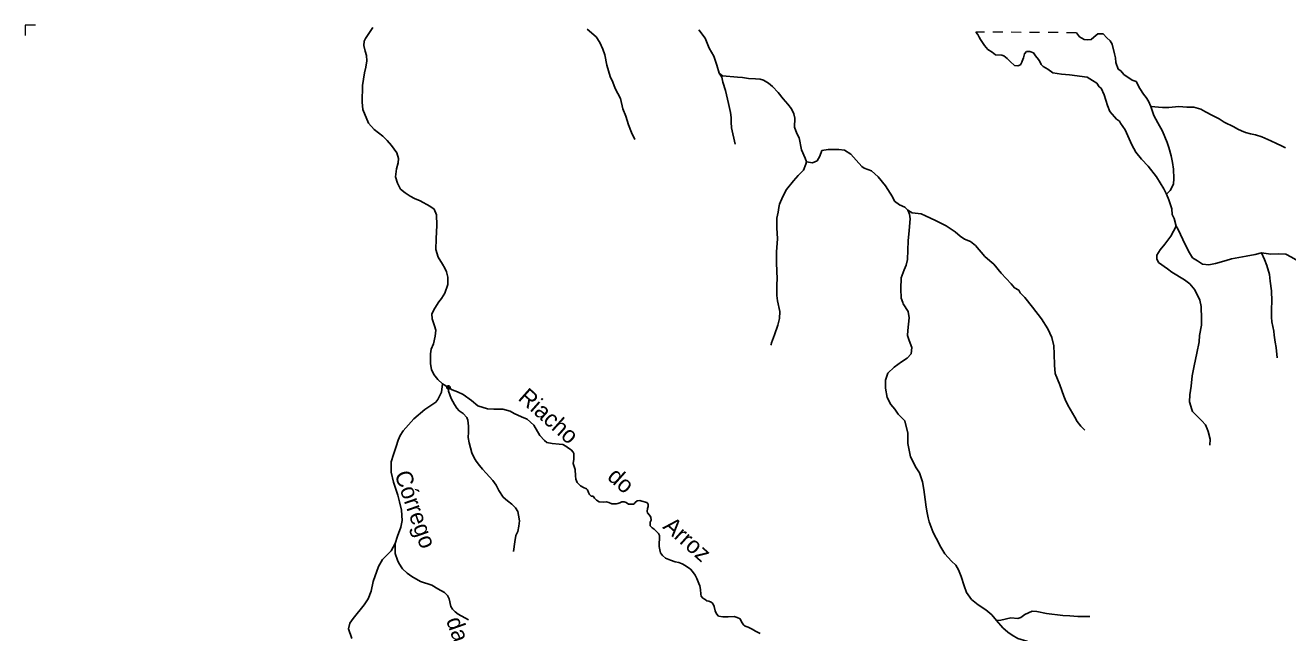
# Model space of a CAD drawing. Extents: x 717.8 to 772.7, y 8672.2 to 8728.
# Drawn here: x 718.16 to 733.27, y 8720.68 to 8727.96 of the extents above; entities that cross this region are included whole.
import ezdxf
from ezdxf.enums import TextEntityAlignment as Align

# ---------------------------------------------------------------- set-up
doc = ezdxf.new("R2010")
doc.units = 0
doc.header["$LTSCALE"] = 0.08
doc.header["$PDMODE"] = 32
doc.header["$PDSIZE"] = 0.04
doc.linetypes.add('LONG_DASHED', pattern=[7.5, 6, -1.5])
doc.linetypes.add('SHORT_DASHED', pattern=[2.7, 1.5, -1.2])
for name, color, linetype, lineweight in [('3', 7, 'LONG_DASHED', 25), ('62', 7, 'SHORT_DASHED', 13), ('63', 7, 'Continuous', 13), ('9', 7, 'LONG_DASHED', 25)]:
    doc.layers.add(name, color=color, linetype=linetype, lineweight=lineweight)
doc.layers.add('61', color=7, linetype='Continuous')

msp = doc.modelspace()

# ---------------------------------------------------------------- linework, layer by layer
at = {"layer": '3'}
for points in [[(729.5397, 8727.8794), (729.5617, 8727.8497), (729.5791, 8727.8187), (729.597, 8727.7887), (729.6416, 8727.7164), (729.6813, 8727.6679), (729.7347, 8727.6398), (729.7754, 8727.6068), (729.8491, 8727.6029), (729.8763, 8727.5932), (729.9162, 8727.5606), (729.9509, 8727.5262), (730.0014, 8727.4787), (730.0408, 8727.4753), (730.0745, 8727.487), (730.0918, 8727.5192), (730.0953, 8727.5317), (730.1113, 8727.5704), (730.1237, 8727.6172), (730.146, 8727.6441), (730.1864, 8727.6477), (730.2292, 8727.63), (730.2531, 8727.5941), (730.2889, 8727.5513), (730.3044, 8727.5246), (730.3228, 8727.4884), (730.3441, 8727.4647), (730.4023, 8727.4329), (730.4604, 8727.3889), (730.5631, 8727.3733), (730.6619, 8727.3676), (730.8702, 8727.3388), (730.9371, 8727.2981), (730.9874, 8727.2669), (731.0151, 8727.2208), (731.0384, 8727.2073), (731.0774, 8727.1266), (731.1164, 8726.999), (731.144, 8726.9253), (731.1978, 8726.8626), (731.2233, 8726.8357), (731.2588, 8726.8116), (731.2694, 8726.7875), (731.3261, 8726.706), (731.4068, 8726.5266), (731.4535, 8726.4401), (731.5226, 8726.3582), (731.6004, 8726.2712), (731.7036, 8726.143), (731.7892, 8726), (731.8214, 8725.9366)], [(731.6344, 8726.9883), (731.6056, 8727.0505), (731.5785, 8727.0961), (731.545, 8727.1365), (731.5028, 8727.2046), (731.4597, 8727.2855), (731.4098, 8727.3038), (731.3111, 8727.3709), (731.2733, 8727.4132), (731.2443, 8727.4359), (731.2163, 8727.5142), (731.2101, 8727.5703), (731.1985, 8727.6188), (731.1728, 8727.7335), (731.1492, 8727.7735), (731.1074, 8727.8101), (731.0617, 8727.8565), (731.0009, 8727.8559), (730.9504, 8727.8162), (730.9204, 8727.79), (730.8816, 8727.7849), (730.8347, 8727.79), (730.7796, 8727.8223), (730.7433, 8727.8704)], [(731.8214, 8725.9366), (731.864, 8725.9813), (731.9058, 8726.0583), (731.9089, 8726.1241), (731.9051, 8726.2374), (731.8938, 8726.3169), (731.8773, 8726.3978), (731.848, 8726.4953), (731.8282, 8726.5539), (731.7745, 8726.6933), (731.7198, 8726.7934), (731.6718, 8726.8797), (731.6344, 8726.9883)]]:
    msp.add_lwpolyline(points, dxfattribs=at)
at = {"layer": '62'}
msp.add_line((730.7433, 8727.8704), (729.5397, 8727.8794), dxfattribs=at)
at = {"layer": '63'}
msp.add_lwpolyline([(718.2841, 8727.9605), (718.1609, 8727.9605), (718.1609, 8727.8391)], dxfattribs=at)
at = {"layer": '9'}
msp.add_line((723.1552, 8723.6644), (723.227, 8723.6225), dxfattribs=at)
for points in [[(722.322, 8727.9322), (722.2324, 8727.8021), (722.2195, 8727.7681), (722.2135, 8727.7167), (722.2294, 8727.6501), (722.246, 8727.5995), (722.2483, 8727.5344), (722.2369, 8727.4588), (722.2231, 8727.3923), (722.1974, 8727.2388), (722.195, 8727.04), (722.2021, 8726.9507), (722.2698, 8726.7889), (722.3393, 8726.7126), (722.4415, 8726.6316), (722.4928, 8726.578), (722.5461, 8726.5218), (722.6097, 8726.4323), (722.6294, 8726.3627), (722.6233, 8726.3113), (722.6044, 8726.2402), (722.5932, 8726.1457), (722.6166, 8726.0686), (722.6514, 8725.9975), (722.7074, 8725.9517), (722.7671, 8725.912), (722.8192, 8725.884), (722.8896, 8725.8568), (723.0027, 8725.795), (723.0541, 8725.7564), (723.0828, 8725.6914), (723.0864, 8725.5662), (723.0789, 8725.4021), (723.0774, 8725.2735), (723.1053, 8725.1805), (723.1536, 8725.0986), (723.1819, 8725.0491), (723.2034, 8725.0053), (723.22, 8724.9426), (723.2177, 8724.8548), (723.185, 8724.7529), (723.1427, 8724.6864), (723.1112, 8724.6466), (723.0656, 8724.5714), (723.0297, 8724.5031), (723.0306, 8724.4419), (723.058, 8724.3606), (723.0759, 8724.3076), (723.0688, 8724.2369), (723.0477, 8724.1452), (723.0208, 8724.0814), (723.0118, 8724.0236), (723.0119, 8723.9035), (723.0231, 8723.8363), (723.0511, 8723.7781), (723.0984, 8723.7185), (723.1552, 8723.6644)], [(725.4572, 8726.591), (725.417, 8726.6763), (725.3822, 8726.7678), (725.3479, 8726.8732), (725.3139, 8726.9585), (725.285, 8727.0834), (725.2205, 8727.2033), (725.194, 8727.2796), (725.1626, 8727.3463), (725.124, 8727.4836), (725.0971, 8727.6047), (725.0753, 8727.6749), (725.0367, 8727.7542), (724.9966, 8727.8208), (724.8886, 8727.913)], [(726.4674, 8727.3874), (726.4401, 8727.4832), (726.4051, 8727.5884), (726.3491, 8727.6864), (726.3001, 8727.8055), (726.2233, 8727.9038)], [(726.6587, 8726.5378), (726.6148, 8726.7321), (726.6096, 8726.7982), (726.609, 8726.8538), (726.602, 8726.9159), (726.5803, 8727.0224), (726.5423, 8727.1791), (726.5119, 8727.2774), (726.4973, 8727.3383), (726.4674, 8727.3874)], [(727.5112, 8726.3234), (727.4969, 8726.3665), (727.4535, 8726.4666), (727.4249, 8726.6118), (727.3978, 8726.6646), (727.3708, 8726.738), (727.3722, 8726.8457), (727.3605, 8726.9), (727.3349, 8726.9608), (727.2872, 8727.0165), (727.2315, 8727.0789), (727.1714, 8727.1566), (727.1055, 8727.2268), (727.0586, 8727.2671), (726.9985, 8727.3031), (726.958, 8727.3133), (726.9008, 8727.3202), (726.8174, 8727.3219), (726.7468, 8727.334), (726.6879, 8727.3381), (726.5084, 8727.3564), (726.4674, 8727.3874)], [(733.2448, 8726.4901), (733.1997, 8726.5172), (733.1366, 8726.5443), (733.0699, 8726.5773), (732.9611, 8726.6224), (732.886, 8726.6482), (732.8277, 8726.6608), (732.7657, 8726.6765), (732.7178, 8726.6974), (732.6758, 8726.7159), (732.6275, 8726.7429), (732.5129, 8726.7986), (732.4527, 8726.8386), (732.3722, 8726.8779), (732.288, 8726.9229), (732.2346, 8726.9568), (732.1498, 8726.9778), (732.0636, 8726.9809), (731.968, 8726.9874), (731.8479, 8726.9767), (731.7741, 8726.9752), (731.6344, 8726.9883)], [(728.7248, 8725.7465), (728.6892, 8725.7801), (728.6241, 8725.8074), (728.5648, 8725.8522), (728.5413, 8725.9064), (728.457, 8726.0361), (728.3719, 8726.1454), (728.2909, 8726.2158), (728.2026, 8726.2466), (728.174, 8726.2678), (728.1059, 8726.3456), (728.0436, 8726.4159), (727.9671, 8726.464), (727.9006, 8726.4717), (727.773, 8726.4725), (727.6973, 8726.4585), (727.6705, 8726.3918), (727.639, 8726.3368), (727.584, 8726.3133), (727.5112, 8726.3234)], [(727.5112, 8726.3234), (727.5053, 8726.2946), (727.4769, 8726.2249), (727.4136, 8726.161), (727.3567, 8726.0965), (727.2743, 8725.9916), (727.2281, 8725.9081), (727.1892, 8725.8189), (727.1797, 8725.7774), (727.1734, 8725.7196), (727.1588, 8725.6513), (727.1554, 8725.5324), (727.1643, 8725.4004), (727.1549, 8725.2449), (727.1549, 8725.1125), (727.1603, 8724.9225), (727.1574, 8724.8549), (727.1574, 8724.7214), (727.1673, 8724.6589), (727.195, 8724.5307), (727.1892, 8724.4463), (727.1684, 8724.3683), (727.1292, 8724.2505), (727.0922, 8724.1551), (727.0882, 8724.1346), (727.0859, 8724.1289)], [(731.9365, 8725.5542), (731.912, 8725.645), (731.8906, 8725.6939), (731.8848, 8725.761), (731.8484, 8725.8709), (731.8214, 8725.9366)], [(729.7852, 8720.83), (729.7311, 8720.8969), (729.6597, 8720.9583), (729.5679, 8721.0175), (729.4869, 8721.0822), (729.4283, 8721.1678), (729.401, 8721.2461), (729.3626, 8721.3571), (729.3336, 8721.4372), (729.2982, 8721.4917), (729.2496, 8721.5429), (729.169, 8721.6275), (729.1204, 8721.707), (729.0641, 8721.818), (729.0297, 8721.8831), (728.979, 8722.0123), (728.9704, 8722.0616), (728.9557, 8722.1219), (728.9453, 8722.1899), (728.9345, 8722.2815), (728.9182, 8722.4001), (728.9025, 8722.4932), (728.8661, 8722.5996), (728.8264, 8722.6589), (728.7555, 8722.7911), (728.7237, 8722.95), (728.7236, 8723.074), (728.6912, 8723.223), (728.6084, 8723.303), (728.5679, 8723.3617), (728.5238, 8723.4171), (728.4797, 8723.5016), (728.4575, 8723.6121), (728.4589, 8723.7083), (728.4859, 8723.7946), (728.5615, 8723.8648), (728.6479, 8723.9295), (728.7175, 8723.9712), (728.7636, 8724.0255), (728.7727, 8724.1003), (728.7433, 8724.1824), (728.722, 8724.2422), (728.7241, 8724.304), (728.7433, 8724.457), (728.7288, 8724.5325), (728.6693, 8724.6243), (728.6639, 8724.6404), (728.645, 8724.6909), (728.6423, 8724.8024), (728.6461, 8724.9351), (728.6806, 8725.0324), (728.7049, 8725.0881), (728.7211, 8725.156), (728.7292, 8725.379), (728.7414, 8725.5007), (728.7525, 8725.6426), (728.7434, 8725.6973), (728.7248, 8725.7465)], [(730.8437, 8723.1092), (730.7945, 8723.1582), (730.7514, 8723.2142), (730.7263, 8723.2673), (730.6416, 8723.4107), (730.6087, 8723.4766), (730.5919, 8723.5187), (730.5452, 8723.6551), (730.4895, 8723.7909), (730.4809, 8723.8886), (730.4755, 8724.0235), (730.4721, 8724.1195), (730.449, 8724.219), (730.4021, 8724.3239), (730.326, 8724.4423), (730.2177, 8724.5827), (730.1257, 8724.7013), (730.071, 8724.756), (730.0549, 8724.7863), (730.0016, 8724.8161), (729.9635, 8724.8631), (729.8445, 8724.9926), (729.754, 8725.0981), (729.7055, 8725.1377), (729.6472, 8725.1905), (729.5346, 8725.3211), (729.4756, 8725.3706), (729.4047, 8725.3987), (729.352, 8725.4358), (729.2931, 8725.4874), (729.1862, 8725.5573), (729.0554, 8725.6236), (728.936, 8725.6795), (728.8833, 8725.7014), (728.7791, 8725.7144), (728.7248, 8725.7465)], [(732.3416, 8722.9313), (732.3434, 8723.0012), (732.3195, 8723.0931), (732.3086, 8723.1259), (732.2884, 8723.1739), (732.2455, 8723.2234), (732.1343, 8723.3353), (732.1266, 8723.3583), (732.0984, 8723.4513), (732.0992, 8723.532), (732.116, 8723.6371), (732.1278, 8723.7606), (732.1513, 8723.8792), (732.1858, 8724.0322), (732.2144, 8724.1685), (732.2161, 8724.2424), (732.2413, 8724.3686), (732.2397, 8724.4443), (732.2355, 8724.5897), (732.2195, 8724.6654), (732.1606, 8724.7899), (732.101, 8724.8621), (732.0365, 8724.9104), (731.8842, 8725.0034), (731.8328, 8725.0408), (731.7278, 8725.1192), (731.7051, 8725.1632), (731.7051, 8725.2077), (731.7471, 8725.2683), (731.8002, 8725.3379), (731.8716, 8725.4329), (731.9365, 8725.5542)], [(731.9365, 8725.5542), (731.9626, 8725.5148), (732.016, 8725.394), (732.0859, 8725.2557), (732.1331, 8725.1761), (732.1911, 8725.1376), (732.2523, 8725.0999), (732.3267, 8725.0909), (732.4101, 8725.1062), (732.5356, 8725.1412), (732.599, 8725.1618), (732.7767, 8725.195), (732.8843, 8725.2147), (732.9591, 8725.2348)], [(733.1446, 8723.9779), (733.1334, 8724.0985), (733.1218, 8724.1641), (733.1123, 8724.2483), (733.1067, 8724.2949), (733.0834, 8724.4061), (733.0785, 8724.4653), (733.0785, 8724.559), (733.0825, 8724.6551), (733.0798, 8724.7797), (733.0628, 8724.8945), (733.0546, 8724.9758), (733.0241, 8725.0812), (732.9948, 8725.1562), (732.9591, 8725.2348)], [(733.9818, 8724.0121), (733.9155, 8724.1229), (733.8999, 8724.2479), (733.904, 8724.3603), (733.9087, 8724.4377), (733.9038, 8724.5924), (733.8842, 8724.6408), (733.8599, 8724.665), (733.7704, 8724.7214), (733.7217, 8724.7601), (733.6926, 8724.7988), (733.6293, 8724.881), (733.563, 8724.9779), (733.4599, 8725.0998), (733.318, 8725.181), (733.251, 8725.2182), (733.1676, 8725.221), (733.0707, 8725.2174), (732.9591, 8725.2348)], [(722.6255, 8722.9902), (722.6468, 8723.0456), (722.6837, 8723.1031), (722.8128, 8723.2464), (722.9426, 8723.3564), (723.0753, 8723.4437), (723.1009, 8723.4778), (723.12, 8723.5189), (723.1441, 8723.5644), (723.1552, 8723.6644)], [(724.0061, 8721.6565), (724.0199, 8721.7711), (724.0338, 8721.8483), (724.0571, 8721.8974), (724.071, 8721.9605), (724.0779, 8722.0236), (724.0661, 8722.0915), (724.0591, 8722.136), (724.0311, 8722.178), (723.9844, 8722.2249), (723.9332, 8722.2623), (723.8818, 8722.3091), (723.8293, 8722.3886), (723.7989, 8722.4495), (723.7569, 8722.5057), (723.7173, 8722.5524), (723.6776, 8722.5945), (723.6356, 8722.6413), (723.5983, 8722.6858), (723.5586, 8722.7395), (723.533, 8722.7793), (723.5049, 8722.8402), (723.4734, 8722.9571), (723.4639, 8723.0225), (723.4669, 8723.0867), (723.4651, 8723.1579), (723.4592, 8723.2308), (723.4474, 8723.2635), (723.4008, 8723.3079), (723.3565, 8723.3431), (723.3261, 8723.3735), (723.2982, 8723.418), (723.2582, 8723.4881), (723.2291, 8723.5789), (723.227, 8723.6225)], [(724.7456, 8722.5615), (724.7422, 8722.6383), (724.7194, 8722.7095), (724.7274, 8722.7628), (724.7294, 8722.8291), (724.7203, 8722.8456), (724.6965, 8722.8739), (724.6628, 8722.8957), (724.6309, 8722.9176), (724.5962, 8722.9377), (724.5514, 8722.9432), (724.4674, 8722.9492), (724.4054, 8722.9624), (724.3762, 8722.987), (724.3223, 8723.0464), (724.2502, 8723.1697), (724.1708, 8723.2427), (724.0995, 8723.2702), (724.0119, 8723.3086), (723.9635, 8723.3369), (723.8783, 8723.36), (723.77, 8723.3606), (723.6951, 8723.3661), (723.5765, 8723.4008), (723.5013, 8723.4642), (723.4033, 8723.5363), (723.3366, 8723.5676), (723.2713, 8723.5953), (723.227, 8723.6225)], [(722.5902, 8721.7512), (722.6186, 8721.8405), (722.6573, 8721.9483), (722.6737, 8722.0292), (722.6666, 8722.152), (722.6414, 8722.2504), (722.6198, 8722.3325), (722.5687, 8722.4863), (722.5403, 8722.6084), (722.5396, 8722.7305), (722.5674, 8722.8199), (722.6019, 8722.9148), (722.6255, 8722.9902)], [(726.9576, 8720.6738), (726.9019, 8720.704), (726.8617, 8720.7268), (726.8152, 8720.7496), (726.7778, 8720.7615), (726.7568, 8720.7789), (726.7356, 8720.8156), (726.7175, 8720.8501), (726.6819, 8720.8674), (726.6463, 8720.8784), (726.5742, 8720.8757), (726.5103, 8720.8729), (726.461, 8720.8821), (726.4345, 8720.9095), (726.4208, 8720.9451), (726.4071, 8720.998), (726.3925, 8721.0327), (726.3697, 8721.0501), (726.345, 8721.062), (726.3176, 8721.0674), (726.2994, 8721.0839), (726.2729, 8721.0994), (726.251, 8721.1213), (726.2464, 8721.1451), (726.2428, 8721.2026), (726.2346, 8721.2473), (726.2254, 8721.2738), (726.1981, 8721.3332), (726.1807, 8721.3715), (726.1488, 8721.4155), (726.1259, 8721.4465), (726.0602, 8721.4904), (726.0228, 8721.5096), (725.9835, 8721.5233), (725.9397, 8721.5342), (725.8859, 8721.5525), (725.8247, 8721.5781), (725.79, 8721.6073), (725.7663, 8721.6402), (725.7617, 8721.6566), (725.7507, 8721.7187), (725.7543, 8721.8466), (725.7415, 8721.8731), (725.7178, 8721.8968), (725.6904, 8721.9233), (725.6649, 8721.9407), (725.6429, 8721.9662), (725.6429, 8722.0092), (725.6521, 8722.0311), (725.6502, 8722.0685), (725.6329, 8722.0941), (725.611, 8722.1187), (725.6037, 8722.137), (725.6073, 8722.1726), (725.6174, 8722.1973), (725.6156, 8722.2247), (725.6019, 8722.2457), (725.5434, 8722.2612), (725.5161, 8722.2694), (725.485, 8722.2621), (725.4631, 8722.2429), (725.4458, 8722.2238), (725.4184, 8722.2229), (725.3828, 8722.2219), (725.3526, 8722.242), (725.3308, 8722.2502), (725.3025, 8722.253), (725.2779, 8722.2402), (725.2542, 8722.2301), (725.2368, 8722.2292), (725.182, 8722.2274), (725.1483, 8722.2438), (725.12, 8722.2502), (725.0807, 8722.2484), (725.0287, 8722.2511), (725.0004, 8722.2721), (724.9748, 8722.2959), (724.9575, 8722.3178), (724.9356, 8722.3214), (724.9146, 8722.3388), (724.9018, 8722.3644), (724.8927, 8722.3963), (724.879, 8722.4073), (724.8415, 8722.4219), (724.8078, 8722.4438), (724.7685, 8722.4822), (724.7521, 8722.5251), (724.7456, 8722.5615)], [(722.0712, 8720.6158), (722.0322, 8720.7301), (722.0457, 8720.7998), (722.0854, 8720.8554), (722.2194, 8721.0176), (722.2641, 8721.089), (722.3017, 8721.1822), (722.3274, 8721.2983), (722.3897, 8721.4769), (722.4387, 8721.5606), (722.5415, 8721.663), (722.5902, 8721.7512)], [(723.467, 8720.8374), (723.3426, 8720.9054), (723.3059, 8720.9324), (723.2744, 8720.9661), (723.2557, 8720.9995), (723.2344, 8721.091), (723.2134, 8721.1298), (723.1787, 8721.1658), (723.1003, 8721.2113), (723.0291, 8721.2524), (722.8904, 8721.298), (722.7881, 8721.3592), (722.7317, 8721.3967), (722.675, 8721.4506), (722.6331, 8721.5159), (722.6175, 8721.5528), (722.5904, 8721.6348), (722.5902, 8721.7512)], [(730.9021, 8720.8766), (730.7587, 8720.8787), (730.6655, 8720.8864), (730.5791, 8720.8906), (730.385, 8720.9155), (730.2713, 8720.9363), (730.2143, 8720.9414), (730.1246, 8720.9014), (730.0785, 8720.8682), (730.0402, 8720.8563), (729.9574, 8720.8621), (729.8389, 8720.8335), (729.7852, 8720.83)], [(730.2659, 8720.4695), (730.2301, 8720.522), (730.2045, 8720.5547), (730.1479, 8720.5839), (730.0434, 8720.6148), (729.9748, 8720.6531), (729.9214, 8720.691), (729.861, 8720.7438), (729.7852, 8720.83)]]:
    msp.add_lwpolyline(points, dxfattribs=at)
msp.add_point((723.227, 8723.6225), dxfattribs=at)

# ---------------------------------------------------------------- texts
at = {"layer": '61'}
for s, rotation, p in [('Riacho        do        Arroz', 318.389, (725.1542, 8722.4996)), ('Córrego            da           Gameleira', 289.422, (723.2773, 8720.6026))]:
    msp.add_text(s, height=0.2, rotation=rotation, dxfattribs=at).set_placement(p, align=Align.CENTER)

doc.saveas('drawing.dxf')
